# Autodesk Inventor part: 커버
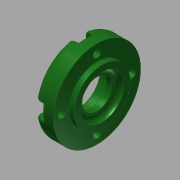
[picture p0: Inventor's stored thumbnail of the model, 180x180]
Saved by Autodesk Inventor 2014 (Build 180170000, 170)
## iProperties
Created: 2015-11
Part Number: 커버
Material: 알루미늄 6061
Document SubType Name: Modeling
Designer: mduedu
Density: 1 g/cm^3
Appearance: 매끄러움 - 짙은 산림 녹색
Author: mduedu
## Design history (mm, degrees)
sketch "스케치1"
  geometry: L1 (-7, 0)-(7, 0); L2 (-7, 0)-(-7, 25); L3 (-7, 25)-(4, 25); L4 (4, 25)-(4, 16); L5 (4, 16)-(7, 16); L6 (7, 16)-(7, 0); 2 further points
  constraints: 12 end point, 3 perpendicular, 2 parallel, 1 coincident, 1 horizontal, 1 midpoint
  dimensions: "d0" = 14 distance of L1.start L1.end; "d1" = 50 diameter of L3 L1; "d2" = 3 distance of L4.end L5.end; "d3" = 32 diameter of L5 L1
revolve "회전1" sketch "스케치1" stored, may be unused: angle "d4" = 90 deg
hole "구멍1" diameter "d7" = 25; stored, may be unused: countersink angle "d11" = 90 deg, drill point angle "d13" = 0 deg; dims "d5" = 10, "d6" = 10, "d8" = 6, "d9" = 4, "d10" = 2, "d12" = 3
hole "구멍2" diameter "d16" = 25; stored, may be unused: countersink angle "d20" = 90 deg, drill point angle "d22" = 0 deg; dims "d17" = 6, "d18" = 4, "d19" = 2, "d21" = 7.7, "d58" = 10, "d59" = 10
hole "구멍3" diameter "d25" = 17; stored, may be unused: countersink angle "d29" = 90 deg, drill point angle "d31" = 0 deg; dims "d23" = 10, "d24" = 10, "d26" = 6, "d27" = 4, "d28" = 2, "d30" = 4.2
chamfer "모따기1" distance "d32" = 0.6; stored, may be unused: second distance "d33" = 2, angle "d34" = 30 deg
fillet "모깎기1" dims "d35" = 0.3
fillet "모깎기2" dims "d36" = 3
fillet "모깎기3" dims "d37" = 3
fillet "모깎기4" dims "d38" = 0.3
sketch "스케치2" dims "d39" = 40
  geometry: 6 further points
  constraints: 2 vertical alignment, 1 coincident, 7 other
  dimensions: "d42" = 360 deg dimension on point (0, 0) point (0, 20) (derived)
sketch "스케치3"
  geometry: 4 further points
hole "구멍4" sketch "스케치3" at (-20, 0), (0, -20), (20, 0), (0, 20) diameter "d44" = 4.5; stored, may be unused: countersink angle "d48" = 90 deg, drill point angle "d50" = 0 deg; dims "d45" = 6, "d46" = 8, "d47" = 4.6, "d49" = 8
sketch "스케치4"
  geometry: L1 (-4, 0)-(-4, -4.678); L2 (4, 0)-(4, -4.678); A1 r 4 centre (0, 0) between (3.621, -1.7) and (-3.621, -1.7) reference; A2 r 25 centre (0, 20) between (-4, -4.678) and (4, -4.678) reference; 1 further point
  constraints: 4 end point, 4 point on circle, 2 tangent, 1 parallel, 1 vertical
extrude "돌출1" cut sketch "스케치4" stored distance "d51" = 0; taper "d52" = 0 deg
fillet "모깎기5" dims "d56" = 0.3
fillet "모깎기6" dims "d57" = 1
node "솔리드1"
pattern_circular "원형 패턴1" dims angle "d54" = 360 deg
